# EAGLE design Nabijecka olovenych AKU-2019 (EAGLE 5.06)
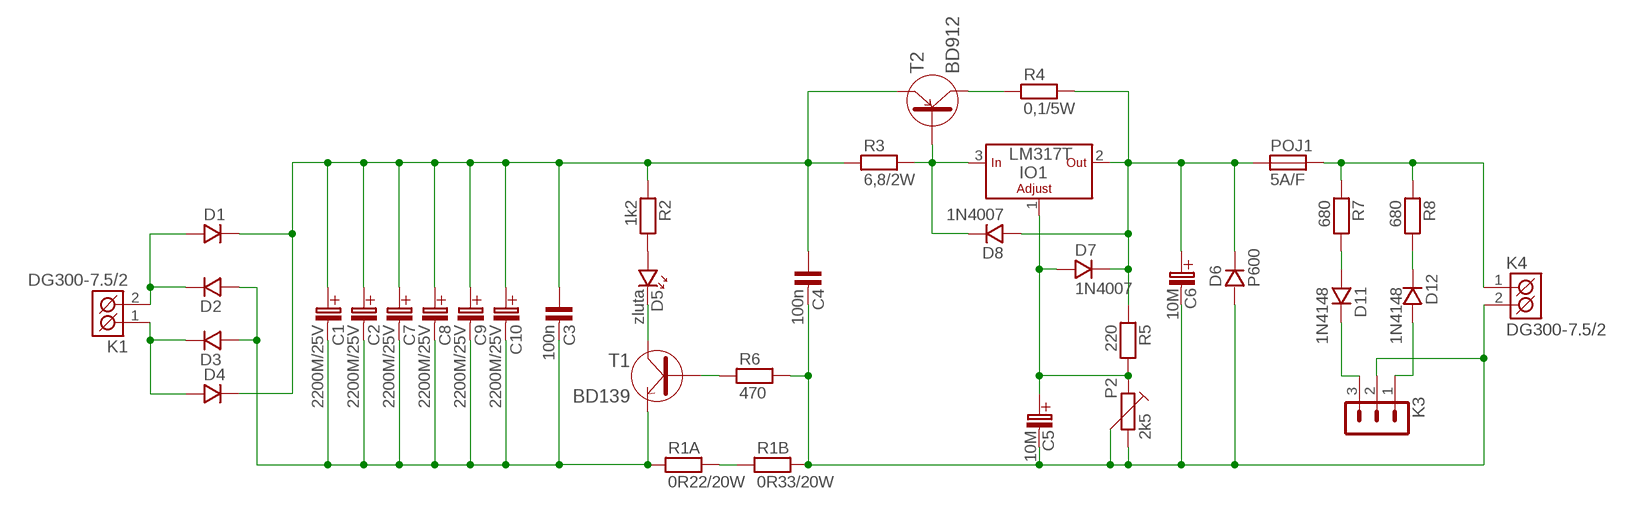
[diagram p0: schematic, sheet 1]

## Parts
C1  2200M/25V  C-EL_7,5+  [C-EL7,5+]
C2  2200M/25V  C-EL_7,5+  [C-EL7,5+]
C3  100n  C-KERAMIK_7,5  [C-7,5]
C4  100n  C-KERAMIK_SMD_1206  [1206]
C5  10M  10M/25V  [C_EL_2]
C6  10M  10M/25V  [C_EL_2]
C7  2200M/25V  C-EL_7,5+  [C-EL7,5+]
C8  2200M/25V  C-EL_7,5+  [C-EL7,5+]
C9  2200M/25V  C-EL_7,5+  [C-EL7,5+]
C10  2200M/25V  C-EL_7,5+  [C-EL7,5+]
D1  D_KY718  [DO-5/1]
D2  D_KY718  [DO-5/1]
D3  D_KY718  [DO-5/1]
D4  D_KY718  [DO-5/1]
D5  zluta  LED_5  [LED_5]
D6  P600  [P6]
D7  1N4007  1N4007_10  [D-10]
D8  1N4007  1N4007_10  [D-10]
D11  1N4148  1N4148_SMD_SOD80  [SOD-80]
D12  1N4148  1N4148_SMD_SOD80  [SOD-80]
IO1  LM317T  [TO-220S]
K1  DG300-7.5/2  [DG300-7.5/2]
K3  PSH02-03P  [PSH02-03]
K4  DG300-7.5/2  [DG300-7.5/2]
P2  2k5  TRIMRPT6V  [PT6V]
POJ1  5A/F  PO_SHH  [POJ_SHH]
R1A  0R22/20W  R__20W  [R-_20W]
R1B  0R33/20W  R__20W  [R-_20W]
R2  1k2  R_SMD_1206  [1206]
R3  6,8/2W  R__2W  [R-_2W]
R4  0,1/5W  R__10W  [R-_10W]
R5  220  R_SMD_1206  [1206]
R6  470  R_SMD_1206  [1206]
R7  680  R_SMD_1206  [1206]
R8  680  R_SMD_1206  [1206]
T1  BD139  [TO-126S]
T2  BD912  [TO-220S]

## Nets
+BAT: K4.1(K1) POJ1.P1 R7.1 R8.1
GND: C4.2 C5.C-(C_EL-) C6.C-(C_EL-) D6.A K3.2 K4.2(K2) P2.2 P2.3 R1B.2 R6.2
MINUS: C1.C-(C_EL-) C2.C-(C_EL-) C3.2 C7.C-(C_EL-) C8.C-(C_EL-) C9.C-(C_EL-) C10.C-(C_EL-) D2.A D3.A R1A.1 T1.1(E)
N$1: R1A.2 R1B.1
N$2: D3.K D4.A K1.1(K1)
N$3: D1.A D2.K K1.2(K2)
N$5: D5.A R2.2
N$6: R6.1 T1.3(B)
N$8: D5.K T1.2(C)
N$10: R4.1 T2.2(C)
N$11: C6.C+(C_EL+) D6.K D7.K D8.A IO1.2(OUT) POJ1.L1 R4.2 R5.1
N$12: D8.K IO1.3(IN) R3.2 T2.1(B)
N$13: D11.K K3.3
N$14: C5.C+(C_EL+) D7.A IO1.1(ADJ) P2.1 R5.2
N$15: D12.A K3.1
N$16: D12.K R8.2
N$17: D11.A R7.2
PLUS: C1.C+(C_EL+) C2.C+(C_EL+) C3.1 C4.1 C7.C+(C_EL+) C8.C+(C_EL+) C9.C+(C_EL+) C10.C+(C_EL+) D1.K D4.K R2.1 R3.1 T2.3(E)

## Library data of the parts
C1 C2 C7-C10 = #PaJa_32:C-EL: Kondenzator - elektrolyticky
C3 C4 = #PaJa_18:C-KERAMIK: Kondenzator - keramicky
C5 C6 = #PaJa_C-el:10M/25V
D1-D4 = #PaJa_32:D: Dioda - univerzální
D5 = #PaJa_18:LED: LED - jednobarevna
D6 = #PaJa_18:P600?: Dioda - usmernovaci, 6A, az 10000V
D7 D8 = #PaJa_18:1N4007: Usmernovaci dioda - 1A, 1000V
D11 D12 = #PaJa_18:1N4148: Univerzalni dioda - 0,15A, 75V
IO1 = #PaJa_18:LM317T: Stabilizator - s nastavitelnym napetim - 1,5A
K1 K4 = #PaJa_konektory:DG300-7.5/2
K3 = #PaJa_18:PSH02-03: Konektory se zamkem - vidlice - 3pin
P2 = #PaJa_32:TRIMR: Trimr
POJ1 = #PaJa_18:PO_SHH: Pojistkove pouzdro
R1A R1B = #PaJa_32:R: Rezistor
R2-R8 = #PaJa_18:R: Rezistor
T1 = #PaJa_18:BD139: Tranzistor NPN - Vykonovy - Ic=1,5A
T2 = #PaJa_18:BD912: Tranzistor PNP - Vykonovy - Ic=15A

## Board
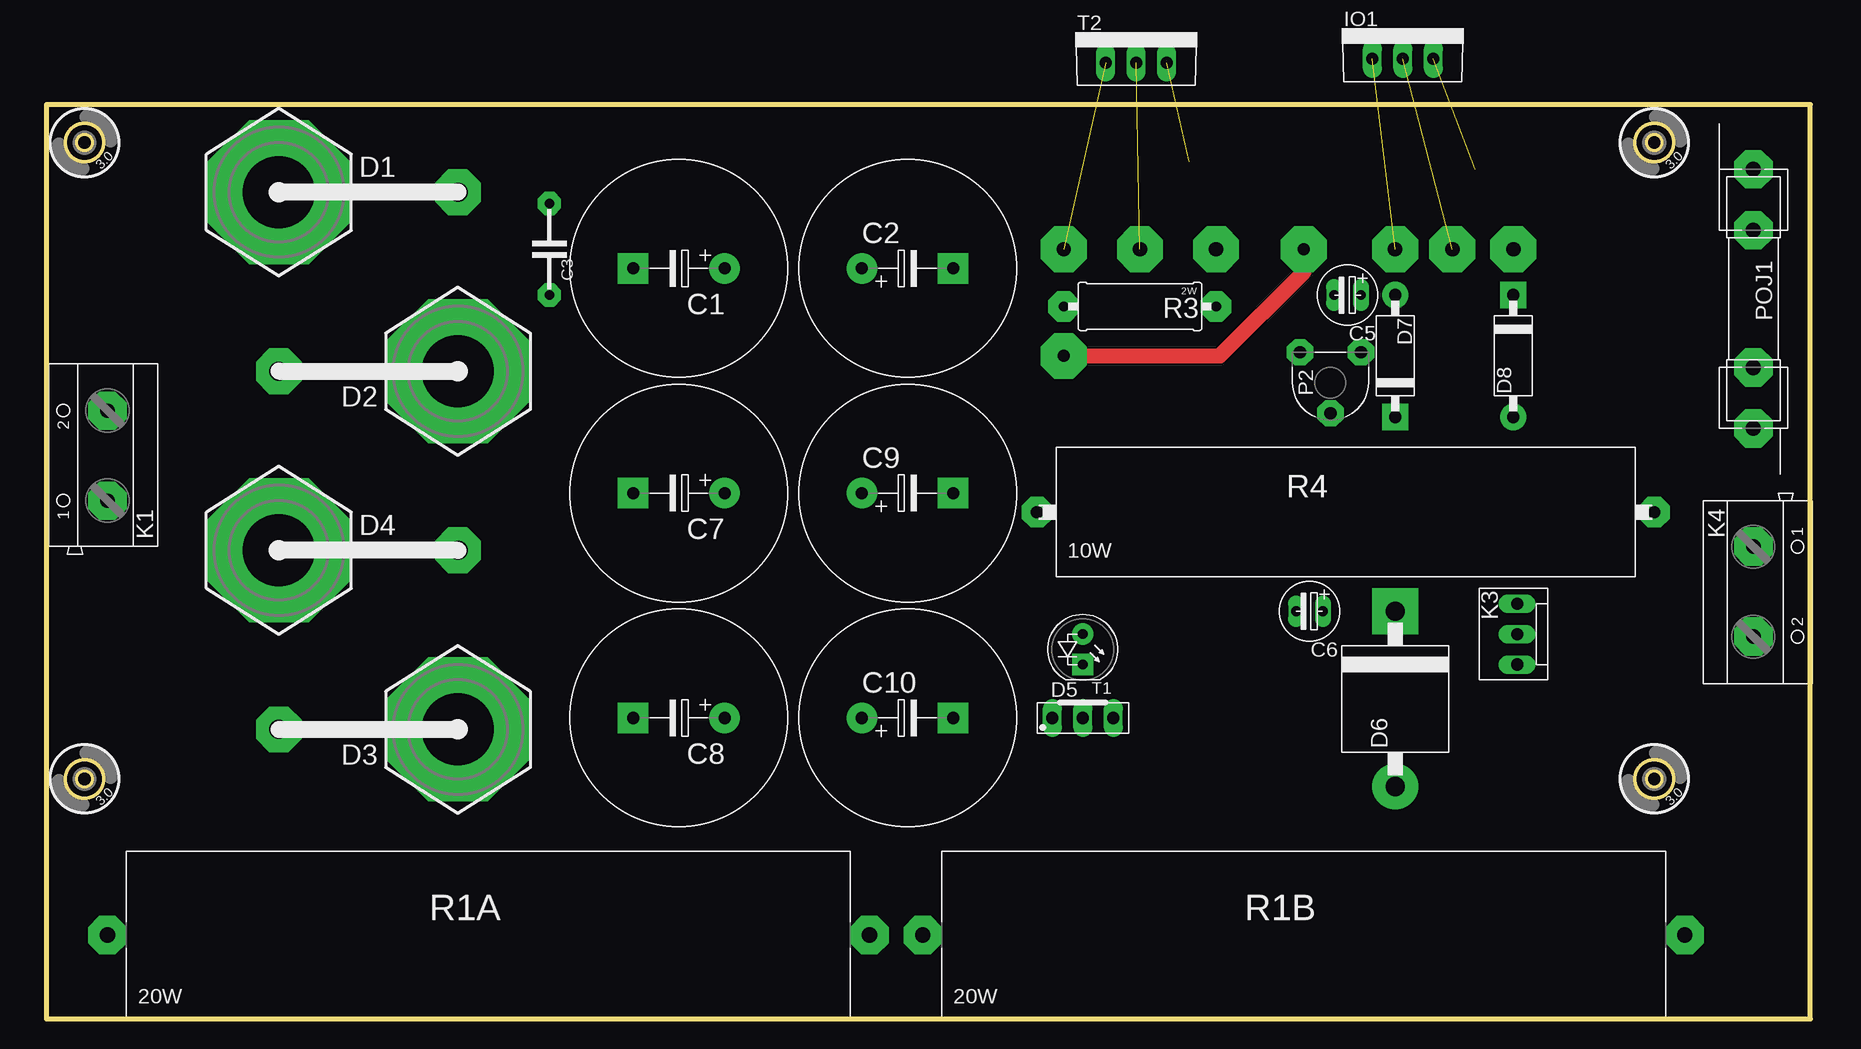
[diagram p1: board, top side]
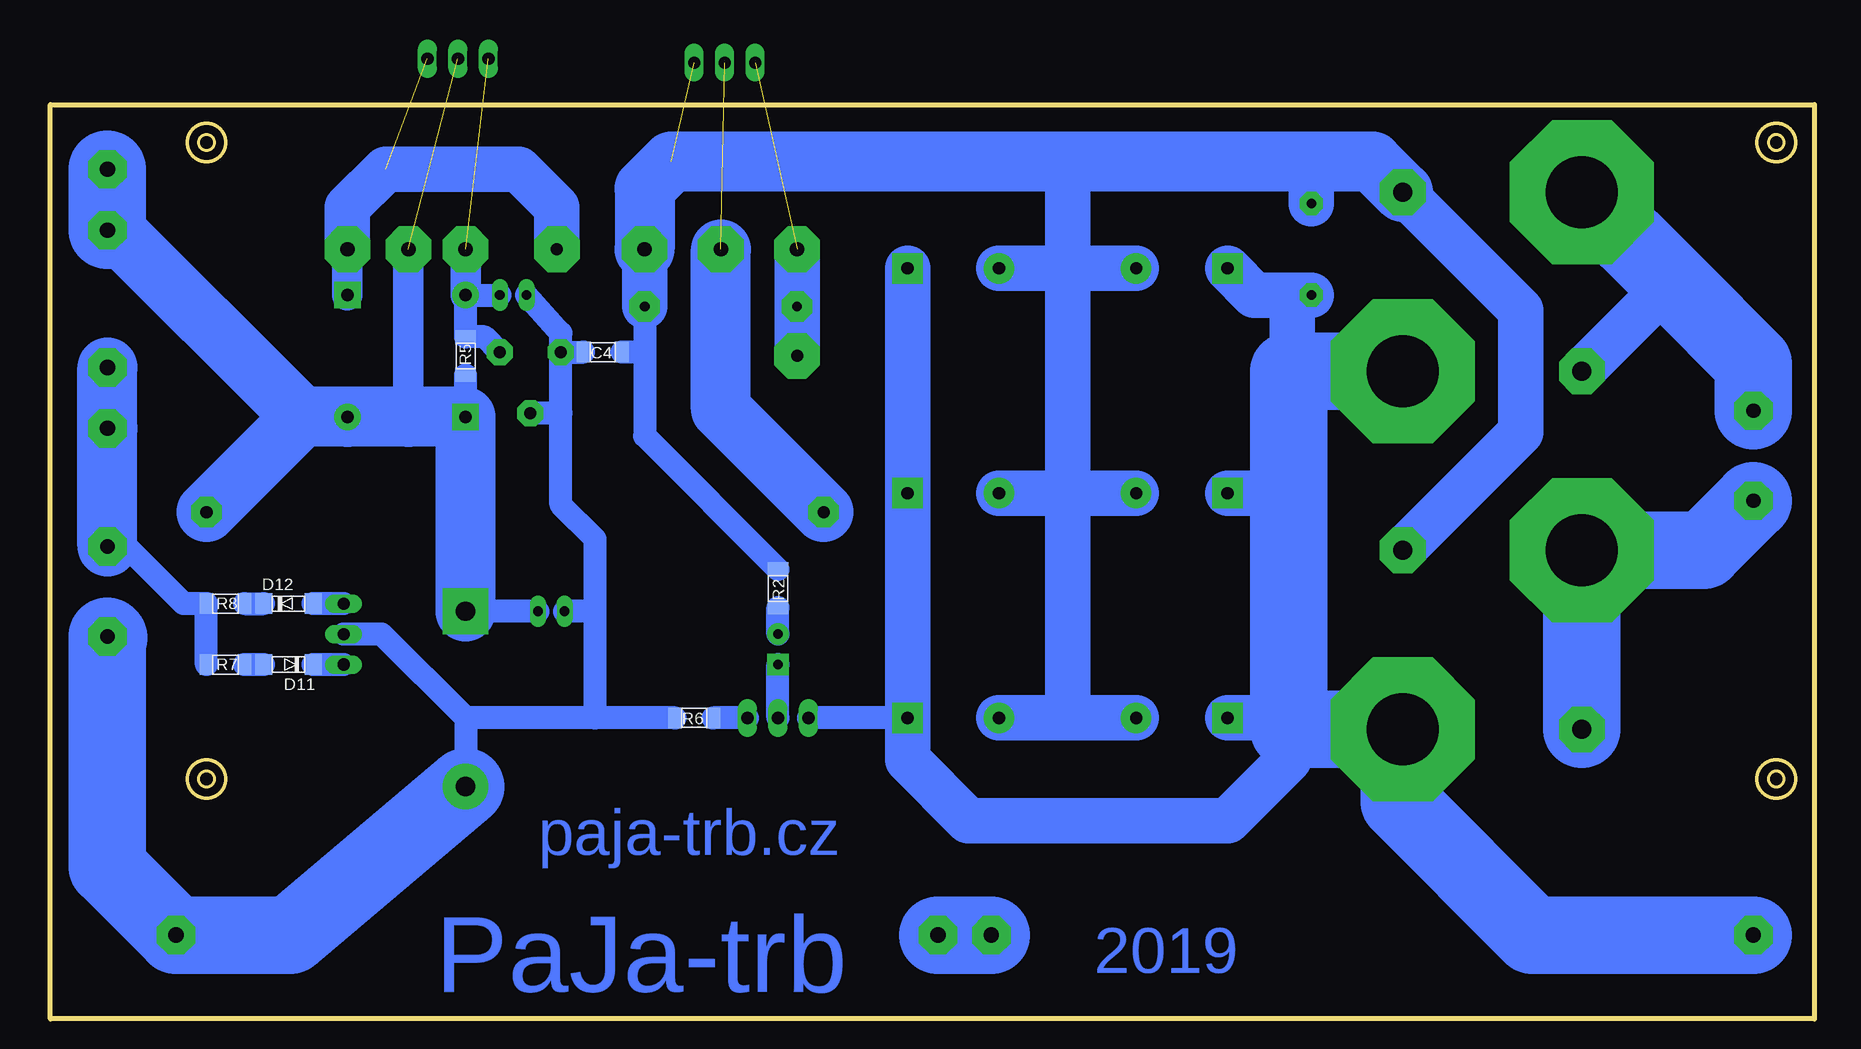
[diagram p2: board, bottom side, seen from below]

Size 146.99 x 76.19 mm. Coordinates in mm from the lower left corner, seen from the top.
Outline: 0,0 146.99,0 146.99,76.19 0,76.19 0,0
Copper layers (1*16): Top 0.035mm / dielectric 1.5mm / Bottom 0.035mm
Design rules "default": minimum track width 10mil, minimum drill 24mil, track to track 8mil, track to pad 8mil, pad to pad 8mil, via to via 8mil, smd to smd 8mil, copper to edge 40mil, drill to drill 8mil, minimum pad ring 10mil, minimum via ring 8mil, stop-mask expansion 4mil, vias tented up to drill 0mil, thermal gap 10mil

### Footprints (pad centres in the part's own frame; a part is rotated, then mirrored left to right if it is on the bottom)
C-EL7,5+ = drill 1.016 pad 2.54 round: C+ -3.81,0 | drill 1.016 pad 2.54 square: C- 3.81,0
C-7,5 = drill 0.813 pad 1.93 octagon: 1 -3.81,0; 2 3.81,0
1206 = smd 1.143 x 1.702: 1 -1.587,0; 2 1.587,0
C_EL_2 = drill 0.813 pad 1.27 long: C+ 0,0; C- 2.223,0
DO-5/1 = drill 6 pad 12 octagon: A 0,0 | drill 1.6 pad 3.81 octagon: K 14.922,0
LED_5 = drill 0.813 pad 1.778 round: A -1.27,0 | drill 0.813 pad 1.778 square: K 1.27,0
P6 = drill 1.6 pad 3.81 round: A -7.303,0 | drill 1.6 pad 3.81 square: K 7.303,0
D-10 = drill 1.016 pad 2.184 round: A -5.08,0 | drill 1.016 pad 2.184 square: K 5.08,0
SOD-80 = smd 1.397 x 1.702: A 1.905,0; K -2.223,0
TO-220S = drill 1.016 pad 1.6 long: 1 -2.54,0; 2 0,0; 3 2.54,0
DG300-7.5/2 = drill 1.2 pad 3.2 octagon: 1 0,0; 2 7.5,0
PSH02-03 = drill 1.016 pad 1.422 long: 1 -2.54,0; 2 0,0; 3 2.54,0
PT6V = drill 1.016 pad 2.184 octagon: 1 -2.54,-2.54; 2 2.54,-2.54; 3 0,2.54
POJ_SHH = drill 1.27 pad 3.2 octagon: L1 -10.795,0; L2 -5.715,0; P1 10.795,0; P2 5.715,0
R-_20W = drill 1.27 pad 3.2 octagon: 1 -31.75,0; 2 31.75,0
R-_2W = drill 0.813 pad 2.54 octagon: 1 -6.35,0; 2 6.35,0
R-_10W = drill 1.016 pad 2.54 octagon: 1 -25.718,0; 2 25.718,0
TO-126S = drill 1.016 pad 1.6 long: 1 -2.54,0; 2 0,0; 3 2.54,0
HOLE_3,0 = hole 3.2: 0,0

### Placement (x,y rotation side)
C1  52.7,62.55 180 top
C2  71.75,62.55 0 top
C3  41.91,64.14 270 top
C4  100.97,55.56 180 bottom
C5  109.54,60.33 180 top
C6  106.36,33.97 180 top
C7  52.7,43.81 180 top
C8  52.7,25.08 180 top
C9  71.75,43.81 0 top
C10  71.75,25.08 0 top
D1  19.37,68.9 0 top
D2  34.29,53.98 180 top
D3  34.29,24.13 180 top
D4  19.37,39.05 0 top
D5  86.36,30.8 270 top
D6  112.39,26.67 90 top
D7  112.39,55.24 270 top
D8  122.24,55.24 90 top
D11  127.32,29.53 180 bottom
D12  127,34.61 0 bottom
IO1  not placed on the board
K1  5.08,43.18 90 top
K3  122.56,32.07 270 top
K4  142.24,39.37 270 top
P2  107,53.02 180 top
POJ1  142.24,60.01 270 top
R1A  36.83,6.99 0 top
R1B  104.78,6.99 0 top
R2  86.36,35.88 270 bottom
R3  91.12,59.37 180 top
R4  108.27,42.23 0 top
R5  112.39,55.24 90 bottom
R6  93.34,25.08 180 bottom
R7  132.4,29.53 0 bottom
R8  132.4,34.61 0 bottom
T1  86.36,25.08 0 top
T2  not placed on the board
U$1  [HOLE_3,0]  3.17,20 0 top
U$2  [HOLE_3,0]  3.17,73.03 0 top
U$3  [HOLE_3,0]  133.99,20 0 top
U$4  [HOLE_3,0]  133.99,73.03 0 top

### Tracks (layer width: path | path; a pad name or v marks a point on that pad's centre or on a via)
+BAT
  Bottom 1.93: R7.1 R8.1 135.89,34.61 140.65,39.37 K4.1
  Bottom 5: K4.1 POJ1.P1 142.24,54.29
GND
  Bottom 1.93: C5.C- 104.46,57.15 P2.2 | 104.46,50.48 P2.2 | 104.46,50.48 P2.3 | 101.6,25.08 101.6,33.97 | 101.6,33.97 101.6,40.01 104.46,42.86 104.46,50.48 | 101.6,25.08 112.39,25.08 | 112.39,25.08 D6.A | K3.2 119.38,32.07 112.39,25.08 | 101.6,33.97 C6.C- | R6.2 101.6,25.08 | P2.2 C4.2
  Bottom 6.452: 142.12,31.75 K4.2 142.24,12.7 R1B.2 127,6.99 D6.A
MINUS
  Bottom 1.93: C10.C- T1.1
  Bottom 3.81: C2.C- C9.C- C10.C- 75.56,21.59 70.48,16.51 48.9,16.51 43.81,21.59 43.81,24.13 | 43.5,60.33 C3.2 | 43.5,53.98 43.5,60.33 | C1.C- 46.67,60.33 43.5,60.33 | 43.81,43.81 C7.C- | 43.81,25.08 C8.C-
  Bottom 6.452: D2.A 43.5,53.98 43.81,53.98 43.81,43.81 43.81,25.08 43.81,24.13 D3.A 34.61,23.81 34.61,18.1 23.5,6.99 R1A.1
N$1
  Bottom 6.452: R1A.2 R1B.1
N$2
  Bottom 6.452: D3.K D4.A 9.21,39.05 K1.1
N$3
  Bottom 3.81: D2.K 12.38,60.96 11.43,60.96
  Bottom 6.452: K1.2 5.08,54.61 11.43,60.96 D1.A
N$5
  Bottom 1.93: D5.A R2.2
N$6
  Bottom 1.93: T1.3 R6.1
N$8
  Bottom 1.93: T1.2 D5.K
N$10  (via drill 1.2 pad 3.81)  (1 unrouted)
  Bottom 5: v91.12,64.14 91.12,50.8 R4.1
N$11  (via drill 1.2 pad 3.81)  (1 unrouted)
  Bottom 1.93: D7.K R5.1 | C6.C+ D6.K
  Bottom 2.54: 117.16,50.16 v117.16,64.14
  Bottom 5: D6.K D7.K 117.16,50.16 D8.A 126.05,50.16 | 126.05,50.16 R4.2 | 126.05,50.16 142.24,66.36 POJ1.L1
  Bottom 6.452: POJ1.L1 142.24,65.72
N$12  (via drill 1 pad 3.81, 1.2 pad 3.81)  (2 unrouted)
  Top 1.27: v104.78,64.14 104.78,62.23 97.79,55.24 v84.77,55.24
  Bottom 2.54: v122.24,64.14 D8.K
  Bottom 3.81: R3.2 v84.77,64.14 v84.77,55.24 | v104.78,64.14 104.78,67.63 107.95,70.8 119.06,70.8 122.24,67.63 v122.24,64.14
N$13
  Bottom 1.93: K3.3 D11.K
N$14  (via drill 1.2 pad 3.81)  (1 unrouted)
  Bottom 1.93: P2.1 110.81,56.83 R5.2 D7.A C5.C+
  Bottom 2.54: D7.A v112.39,64.14
N$15
  Bottom 1.93: K3.1 D12.A
N$16
  Bottom 1.93: R8.2 D12.K
N$17
  Bottom 1.93: D11.A R7.2
PLUS  (via drill 1.2 pad 3.81)  (1 unrouted)
  Bottom 1.93: R2.1 97.47,48.58 97.47,55.88 | R3.1 97.47,55.88 | C4.1 97.79,55.56 97.47,55.88
  Bottom 3.81: D1.K 24.45,59.05 24.45,48.9 D4.K | 62.23,43.81 C7.C+ | 62.23,62.55 62.23,43.81 | 62.23,62.55 C1.C+ | 62.23,62.55 C2.C+ | 62.23,71.44 62.23,62.55 | 62.23,25.08 C8.C+ | 62.23,43.81 62.23,25.08 | 62.23,25.08 C10.C+ | 62.23,43.81 C9.C+ | 41.91,71.44 C3.1 | v97.47,64.14 R3.1
  Bottom 5: D1.K 36.83,71.44 41.91,71.44 62.23,71.44 95.25,71.44 97.47,69.22 v97.47,64.14

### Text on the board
Bottom: paja-trb.cz | 2019 | PaJa-trb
